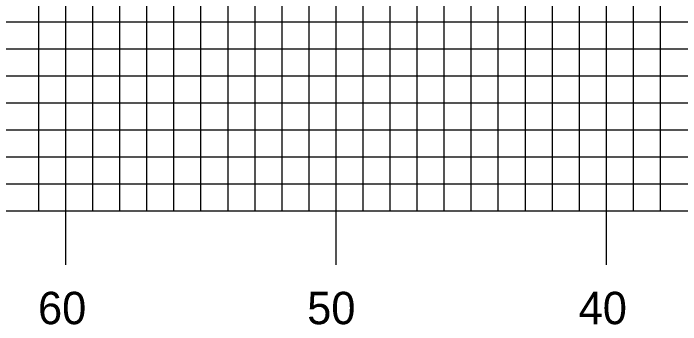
# Model space of a CAD drawing. Extents: x 1804290 to 1804634, y 442591 to 442811.
# Drawn here: x 1804394.23 to 1804418.91, y 442649.45 to 442660.98 of the extents above; entities that cross this region are included whole.
import ezdxf

# ---------------------------------------------------------------- set-up
doc = ezdxf.new("R2010")
doc.units = 0
for name, color, linetype in [('H_V ANNOTATION', 7, 'Continuous'), ('MAJOR', 7, 'Continuous'), ('MINOR', 7, 'Continuous')]:
    doc.layers.add(name, color=color, linetype=linetype)

msp = doc.modelspace()

# ---------------------------------------------------------------- linework, layer by layer
at = {"layer": 'MAJOR'}
for p, q in [((1804396.167, 442653.665), (1804396.167, 442678.665)), ((1804406.167, 442653.665), (1804406.167, 442678.665)), ((1804416.167, 442653.665), (1804416.167, 442678.665)), ((1804316.167, 442658.665), (1804596.167, 442658.665)), ((1804316.167, 442653.665), (1804596.167, 442653.665)), ((1804316.167, 442653.665), (1804596.167, 442653.665)), ((1804396.167, 442651.661), (1804396.167, 442653.665)), ((1804406.167, 442651.661), (1804406.167, 442653.665)), ((1804416.167, 442651.661), (1804416.167, 442653.665))]:
    msp.add_line(p, q, dxfattribs=at)
at = {"layer": 'MINOR'}
for p, q in [((1804395.167, 442653.665), (1804395.167, 442678.665)), ((1804397.167, 442653.665), (1804397.167, 442678.665)), ((1804398.167, 442653.665), (1804398.167, 442678.665)), ((1804399.167, 442653.665), (1804399.167, 442678.665)), ((1804400.167, 442653.665), (1804400.167, 442678.665)), ((1804401.167, 442653.665), (1804401.167, 442678.665)), ((1804402.167, 442653.665), (1804402.167, 442678.665)), ((1804403.167, 442653.665), (1804403.167, 442678.665)), ((1804404.167, 442653.665), (1804404.167, 442678.665)), ((1804405.167, 442653.665), (1804405.167, 442678.665)), ((1804407.167, 442653.665), (1804407.167, 442678.665)), ((1804408.167, 442653.665), (1804408.167, 442678.665)), ((1804409.167, 442653.665), (1804409.167, 442678.665)), ((1804410.167, 442653.665), (1804410.167, 442678.665)), ((1804411.167, 442653.665), (1804411.167, 442678.665)), ((1804412.167, 442653.665), (1804412.167, 442678.665)), ((1804413.167, 442653.665), (1804413.167, 442678.665)), ((1804414.167, 442653.665), (1804414.167, 442678.665)), ((1804415.167, 442653.665), (1804415.167, 442678.665)), ((1804417.167, 442653.665), (1804417.167, 442678.665)), ((1804418.167, 442653.665), (1804418.167, 442678.665)), ((1804316.167, 442660.665), (1804596.167, 442660.665)), ((1804316.167, 442659.665), (1804596.167, 442659.665)), ((1804316.167, 442657.665), (1804596.167, 442657.665)), ((1804316.167, 442656.665), (1804596.167, 442656.665)), ((1804316.167, 442655.665), (1804596.167, 442655.665)), ((1804316.167, 442654.665), (1804596.167, 442654.665))]:
    msp.add_line(p, q, dxfattribs=at)

# ---------------------------------------------------------------- texts
at = {"layer": 'H_V ANNOTATION'}
for s, p in [('60', (1804395.139, 442649.465)), ('50', (1804405.096, 442649.465)), ('40', (1804415.139, 442649.465))]:
    msp.add_text(s, height=1.2, dxfattribs=at).set_placement(p)

doc.saveas('drawing.dxf')
